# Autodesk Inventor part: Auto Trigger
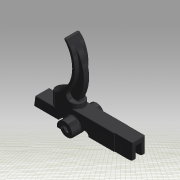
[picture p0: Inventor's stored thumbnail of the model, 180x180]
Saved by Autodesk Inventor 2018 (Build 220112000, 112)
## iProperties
Part Number: Auto Trigger
Material: Steel
Document SubType Name: Modeling
Designer: johne
Density: 7.85 g/cm^3
Appearance: Default
Author: johne
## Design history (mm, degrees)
feature "Solid1"
body "Solid2"
